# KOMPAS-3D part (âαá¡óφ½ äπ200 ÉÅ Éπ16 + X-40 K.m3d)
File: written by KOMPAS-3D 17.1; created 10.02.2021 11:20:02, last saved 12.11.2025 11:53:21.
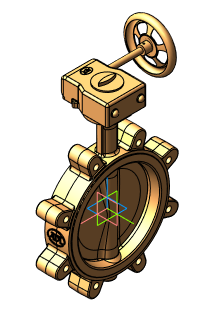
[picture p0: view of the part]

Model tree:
1. Операция без истории:7  (labels: Сталь 20  ГОСТ 1050-2013)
